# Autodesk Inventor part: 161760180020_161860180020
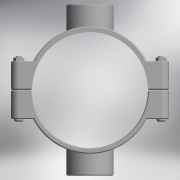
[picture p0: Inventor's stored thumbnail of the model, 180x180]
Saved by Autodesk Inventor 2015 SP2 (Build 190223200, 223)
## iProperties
Created: 2017-05
Part Number: 161760180020_161860180020
Material: Generic
Description: PLASSON DOUBLE SADDLE 180-2"
Document SubType Name: Modeling
Designer: KIM
Density: 1 g/cm^3
Appearance: Default
Author: KIM
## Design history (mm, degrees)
derived "16176.ipt"
feature "Solid1::16176.ipt"
feature "Solid2::16176.ipt"
tag "TaggingFeature1"
body "Solid1"
body "Solid2"
other parameters: "d0" = 198, "d1" = 245, "d4" = 154, "d5" = 0, "d6" = 12.25, "d7" = 245, "d8" = 0.1, "d10" = 0, "d11" = 1.8, "d20" = 1.8, "d23" = 1.8, "d36" = 15, "d37" = 12, "d38" = 98, "d39" = 0, "d40" = 3, "d41" = 5, "d42" = 0, "d44" = 3, "d45" = 0, "d46" = 1.8, "d52" = 56.656, "d54" = 0, "d57" = 0, "d58" = 194.4, "d60" = 0, "d62" = 15, "d63" = 12, "d67" = 266, "d68" = 73.6528, "d69" = 56.656, "d71" = 0, "d74" = 0, "d75" = 1.8, "G_" = 56.656, "A_" = 133, "L_" = 245, "L_1" = 154
